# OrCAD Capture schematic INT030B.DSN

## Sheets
1 PAGE3: size B; title: TUSB542EVM INT030 Rev B: Power; rev: B; note: 6592044
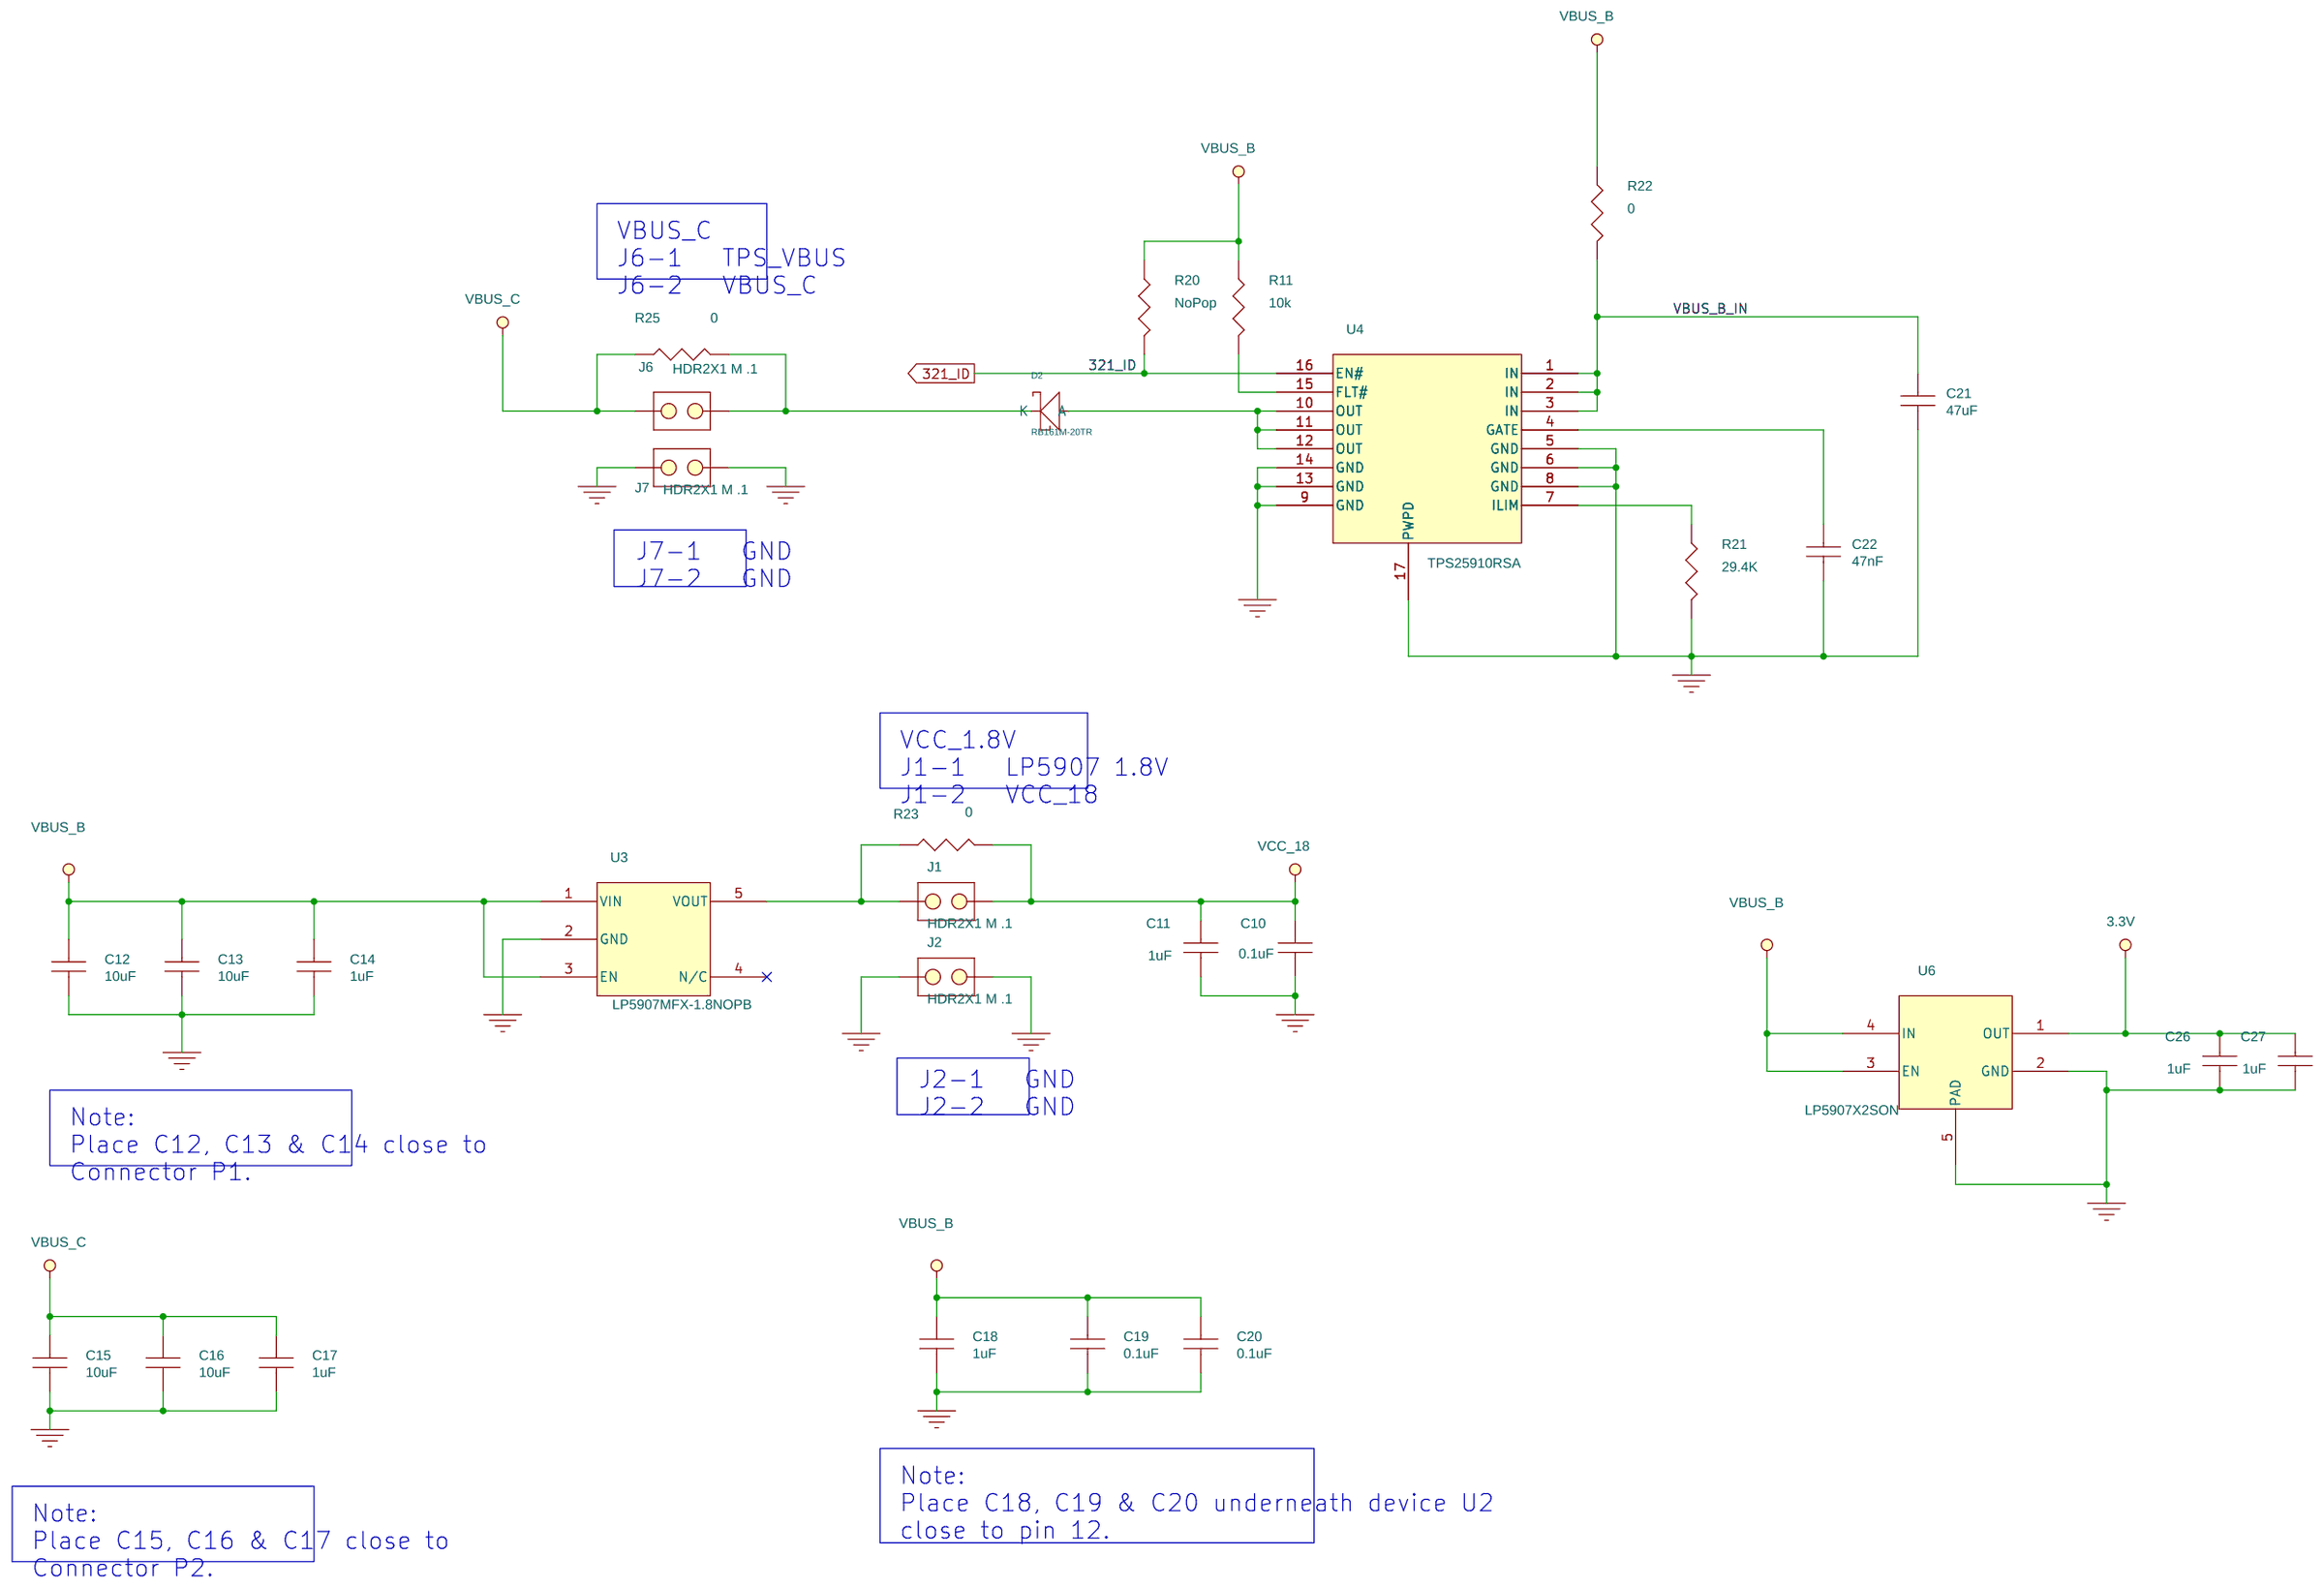
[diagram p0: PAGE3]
2 PAGE2: size C; title: TUSB542EVM INT030 Rev B
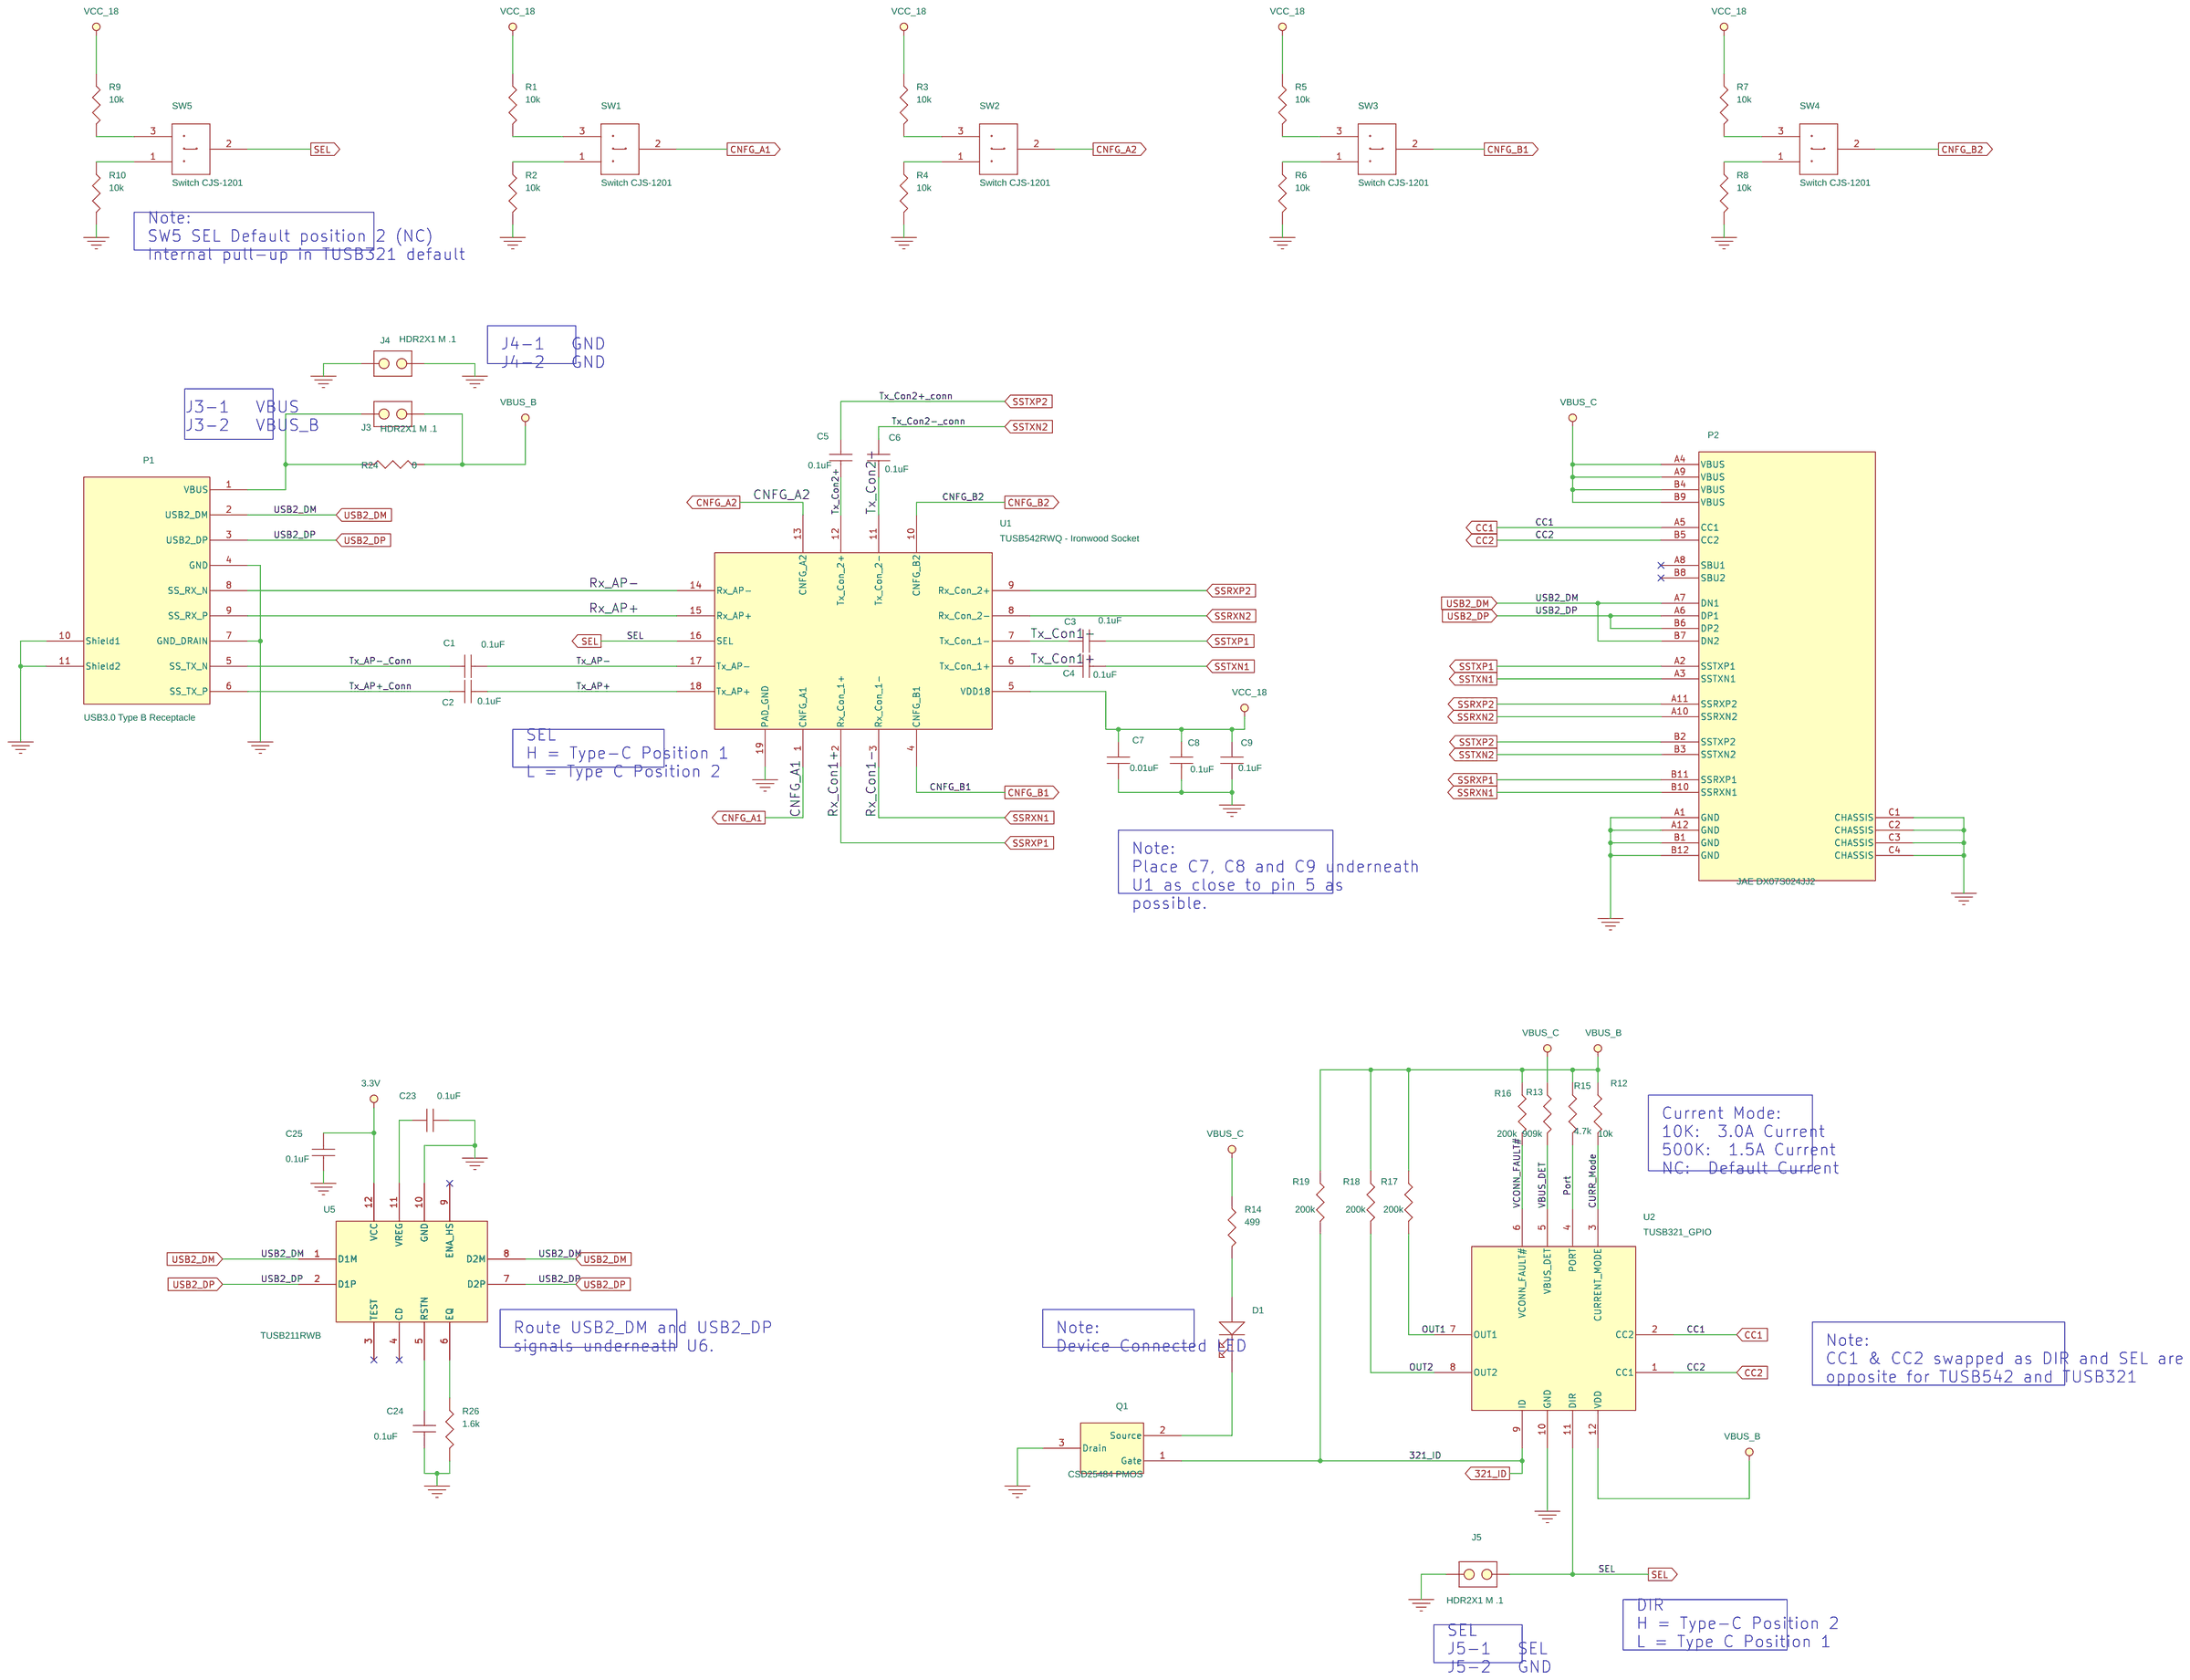
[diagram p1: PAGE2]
3 PAGE1: size B; title: TUSB542EVM INT030 Rev B: Block
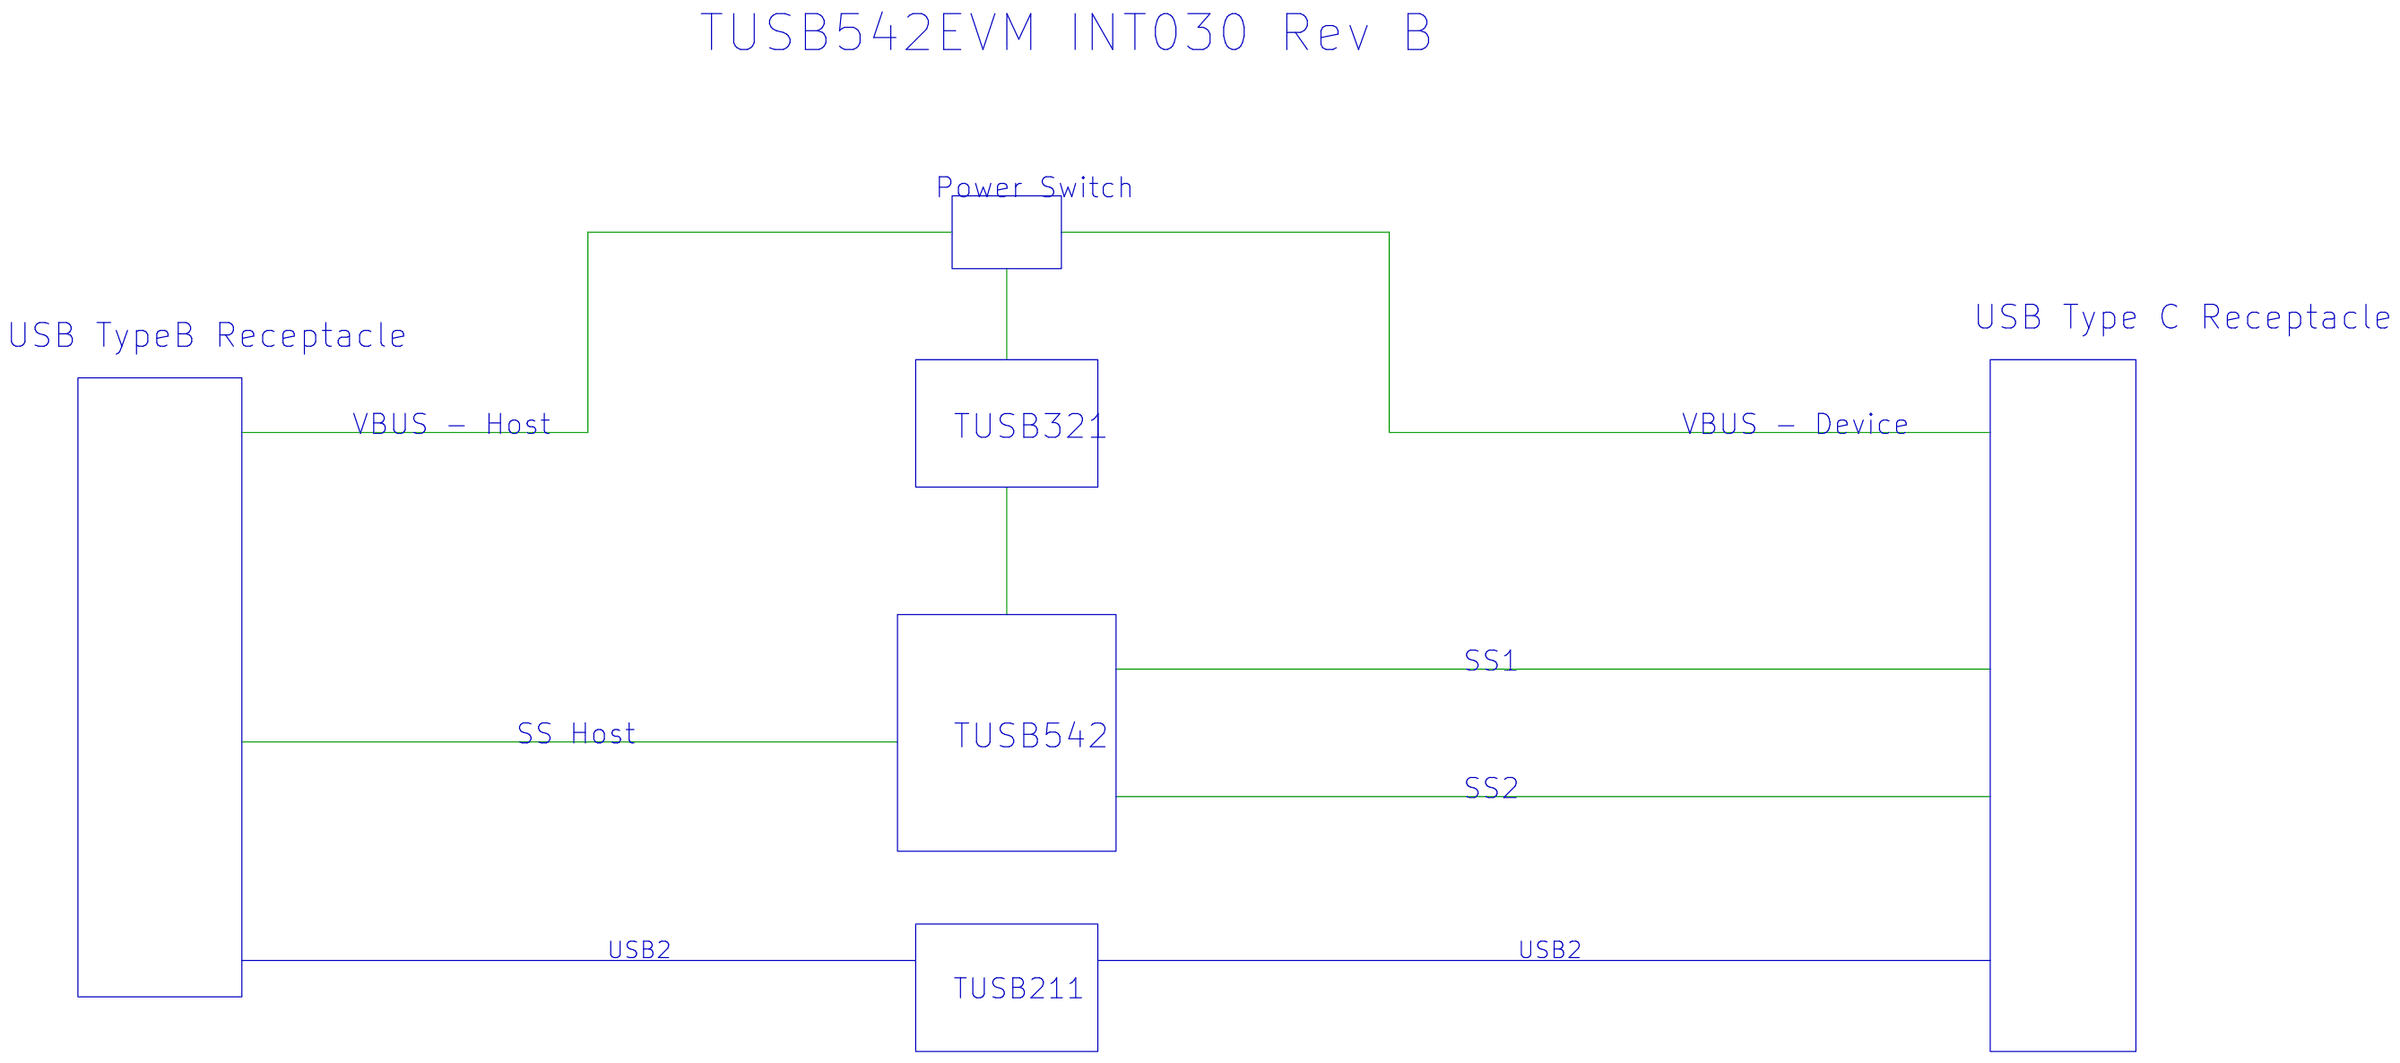
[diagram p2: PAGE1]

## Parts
sheet PAGE2
C1  0.1uF  [0201]
C2  0.1uF  [0201]
C3  0.1uF  [0201]
C4  0.1uF  [0201]
C5  0.1uF  [0201]
C6  0.1uF  [0201]
C7  0.01uF  [0201]
C8  0.1uF  [0201]
C9  0.1uF  [0201]
C23  0.1uF  [0201]
C24  0.1uF  [0201]
C25  0.1uF  [0201]
D1  LED  [LED_0805]
J3  HDR2X1 M .1  [HDR_THVT_1x2_100]
J4  HDR2X1 M .1  [HDR_THVT_1x2_100]
J5  HDR2X1 M .1  [HDR_THVT_1x2_100]
P1  USB3.0 Type B Receptacle  [USB3_TYPEB_AK4AA009]
P2  JAE DX07S024JJ2
Q1  CSD25484 PMOS  [YJJ_DFN_3]
R1  10k  [0402]
R2  10k  [0402]
R3  10k  [0402]
R4  10k  [0402]
R5  10k  [0402]
R6  10k  [0402]
R7  10k  [0402]
R8  10k  [0402]
R9  10k  [0402]
R10  10k  [0402]
R12  10k  [0402]
R13  909k  [0402]
R14  499  [0402]
R15  4.7k  [0402]
R16  200k  [0402]
R17  200k  [0402]
R18  200k  [0402]
R19  200k  [0402]
R24  0  [0805]
R26  1.6k  [0201]
SW1  Switch CJS-1201  [CJS-1200B]
SW2  Switch CJS-1201  [CJS-1200B]
SW3  Switch CJS-1201  [CJS-1200B]
SW4  Switch CJS-1201  [CJS-1200B]
SW5  Switch CJS-1201  [CJS-1200B]
U1  TUSB542RWQ - Ironwood Socket  [SKT_Ironwood_C14524]
U2  TUSB321_GPIO  [RWB]
U5  TUSB211RWB  [RWB]
sheet PAGE3
C10  0.1uF  [0402]
C11  1uF  [0402]
C12  10uF  [0603]
C13  10uF  [0603]
C14  1uF  [0402]
C15  10uF  [0603]
C16  10uF  [0603]
C17  1uF  [0402]
C18  1uF  [0402]
C19  0.1uF  [0201]
C20  0.1uF  [0201]
C21  47uF  [1206]
C22  47nF  [0402]
C26  1uF  [0402]
C27  1uF  [0402]
D2  SCHOTTKY  [SOD_123FL]
J1  HDR2X1 M .1  [HDR_THVT_1x2_100]
J2  HDR2X1 M .1  [HDR_THVT_1x2_100]
J6  HDR2X1 M .1  [HDR_THVT_1x2_100]
J7  HDR2X1 M .1  [HDR_THVT_1x2_100]
R11  10k  [0402]
R20  NoPop  [0402]
R21  29.4K  [0402]
R22  0  [0805]
R23  0  [0805]
R25  0  [0805]
U3  LP5907MFX-1.8NOPB  [DBV_R-PDSO-G5]
U4  TPS25910RSA  [QFN_16_161x161_26]
U6  LP5907X2SON  [DQN_X2SON_4]

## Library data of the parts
C1-C9 C19 C20 C23-C25 = cc0201
D1 = d0805_Green
J1-J7 = HDR2X1_M_.1
P1 = USB_3_0.0_Type_B_Receptacle
P2 = TypeC_JAE_TopMNT
Q1 = CSD25484F4
R1-R10 R12-R19 = r0402
R23-R25 = r0805
R26 = r0201
SW1-SW5 = Switch_CJS-1201
U1 = TUSB542RWQ
U2 = TUSB321_GPIO
U5 = TUSB211RWB
C10 C11 C14 C17 C18 C26 C27 = cc0402
C12 C13 C15 C16 = cc0603
C21 = CAP_NP: 10V Capacitor
C22 = CAP_NP: 6.3V Capacitor
D2 = SCHOTTKY: Diode; $SEC: 1; CDS_LIB: diode; CURRENT: 1A; DEVICE_NAME: RB161M-20TR; DRAWING: @LIGHTNING_BOLT_NB_LIB.NOTE_BOOK(SCH_1):PAGE1; Digi-Key Part Number: RB161M-20CT-ND; Manufacturer: Rohm Semiconductor; Manufacturer Part Number: RB161M-20TR; Manufacturer's Part Number: RB161M-20TR; PHYS_PAGE: 1; ROT: 0; TOLERANCE: NA; VER: 1; VOLTAGE: 20V; XY: (-1750,3700)
R11 R20 R22 = R: Resistor; Tolerance: 5%
R21 = R: Resistor; Tolerance: 1%
U3 = LP5907
U4 = TPS25910RSA
U6 = LP5907X2SON

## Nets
3.3V: C25.2 C26.1 C27.1 U5.12(VCC) U6.1(OUT)
GND: C7.2 C8.2 C9.2 C10.2 C11.2 C12.2 C13.2 C14.2 C15.2 C16.2 C17.2 C18.2 C19.2 C20.2 C21.2 C22.2 C23.2 C24.2 C25.1 C26.2 C27.2 J2.1 J2.2 J4.1 J4.2 J5.2 J7.1 J7.2 P1.4(GND) P1.7(GND_DRAIN) P1.10(Shield1) P1.11(Shield2) P2.A1(GND) P2.A12(GND) P2.B1(GND) P2.B12(GND) P2.C1(CHASSIS) P2.C2(CHASSIS) P2.C3(CHASSIS) P2.C4(CHASSIS) Q1.3(Drain) R2.2 R4.2 R6.2 R8.2 R10.2 R21.2 R26.2 U1.19(PAD_GND) U2.10(GND) U3.2(GND) U4.5(GND) U4.6(GND) U4.8(GND) U4.9(GND) U4.13(GND) U4.14(GND) U4.17(PWPD) U5.10(GND) U6.2(GND) U6.5(PAD)
VBUS_B: C12.1 C13.1 C14.1 C18.1 C19.1 C20.1 J3.2 R11.1 R12.1 R15.1 R16.1 R17.1 R18.1 R19.1 R20.1 R22.1 R24.2 U2.12(VDD) U3.1(VIN) U3.3(EN) U6.3(EN) U6.4(IN)
VBUS_B_IN: C21.1 R22.2 U4.1(IN) U4.2(IN) U4.3(IN)
VBUS_C: C15.1 C16.1 C17.1 J6.1 P2.A4(VBUS) P2.A9(VBUS) P2.B4(VBUS) P2.B9(VBUS) R13.1 R14.1 R25.1
VBUS_DET: R13.2 U2.5(VBUS_DET)
VCC_18: C7.1 C8.1 C9.1 C10.1 C11.1 J1.2 R1.1 R3.1 R5.1 R7.1 R9.1 R23.2 U1.5(VDD18)
321_ID: Q1.1(Gate) R19.2 R20.2 U2.9(ID) U4.16(EN#)
CC1: P2.A5(CC1) U2.2(CC2)
CC2: P2.B5(CC2) U2.1(CC1)
CNFG_A1: SW1.2 U1.1(CNFG_A1)
CNFG_A2: SW2.2 U1.13(CNFG_A2)
CNFG_B1: SW3.2 U1.4(CNFG_B1)
CNFG_B2: SW4.2 U1.10(CNFG_B2)
CURR_Mode: R12.2 U2.3(CURRENT_MODE)
OUT1: R17.2 U2.7(OUT1)
OUT2: R18.2 U2.8(OUT2)
Port: R15.2 U2.4(PORT)
Rx_AP+: P1.9(SS_RX_P) U1.15(Rx_AP+)
Rx_AP-: P1.8(SS_RX_N) U1.14(Rx_AP-)
SEL: J5.1 SW5.2 U1.16(SEL) U2.11(DIR)
SSRXN1: P2.B10(SSRXN1) U1.3(Rx_Con_1-)
SSRXN2: P2.A10(SSRXN2) U1.8(Rx_Con_2-)
SSRXP1: P2.B11(SSRXP1) U1.2(Rx_Con_1+)
SSRXP2: P2.A11(SSRXP2) U1.9(Rx_Con_2+)
SSTXN1: C4.2 P2.A3(SSTXN1)
SSTXN2: C6.1 P2.B3(SSTXN2)
SSTXP1: C3.2 P2.A2(SSTXP1)
SSTXP2: C5.1 P2.B2(SSTXP2)
Tx_AP+: C2.2 U1.18(Tx_AP+)
Tx_AP+_Conn: C2.1 P1.6(SS_TX_P)
Tx_AP-: C1.2 U1.17(Tx_AP-)
Tx_AP-_Conn: C1.1 P1.5(SS_TX_N)
Tx_Con1+: C4.1 U1.6(Tx_Con_1+)
Tx_Con1-: C3.1 U1.7(Tx_Con_1-)
Tx_Con2+: C5.2 U1.12(Tx_Con_2+)
Tx_Con2-: C6.2 U1.11(Tx_Con_2-)
USB2_DM: P1.2(USB2_DM) P2.A7(DN1) P2.B7(DN2) U5.1(D1M) U5.8(D2M)
USB2_DP: P1.3(USB2_DP) P2.A6(DP1) P2.B6(DP2) U5.2(D1P) U5.7(D2P)
VCONN_FAULT#: R16.2 U2.6(VCONN_FAULT#)
N04611: J3.1 P1.1(VBUS) R24.1
N16552543: R1.2 SW1.3
N16552547: R2.1 SW1.1
N16552551: R3.2 SW2.3
N16552555: R4.1 SW2.1
N16552559: R5.2 SW3.3
N16552563: R6.1 SW3.1
N16552567: R7.2 SW4.3
N16552571: R8.1 SW4.1
N16553344: R10.1 SW5.1
N16553348: R9.2 SW5.3
N16554903: D1.2 R14.2
N16554907: D1.1 Q1.2(Source)
N16595246: R11.2 U4.15(FLT#)
N16595298: D2.2(A) U4.10(OUT) U4.11(OUT) U4.12(OUT)
N16595310: R21.1 U4.7(ILIM)
N16595320: C22.1 U4.4(GATE)
N16602154: J1.1 R23.1 U3.5(VOUT)
N16604263: C23.1 U5.11(VREG)
N16604411: C24.1 U5.5(RSTN)
N16604415: R26.1 U5.6(EQ)
N16616318: D2.1(K) J6.2 R25.2

Not connected (* = marked no-connect by the designer): P2 A8(SBU1)* B8(SBU2)*; U3 4(N/C)*; U5 3(TEST)* 4(CD)* 9(ENA_HS)*

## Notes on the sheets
sheet 1
- VBUS_C
  J6-1   TPS_VBUS
  J6-2   VBUS_C
- J7-1   GND
  J7-2   GND
- VCC_1.8V
  J1-1   LP5907 1.8V
  J1-2   VCC_18
- J2-1   GND
  J2-2   GND
- Note:
  Place C12, C13 & C14 close to
  Connector P1.
- Note:
  Place C18, C19 & C20 underneath device U2
  close to pin 12.
- Note:
  Place C15, C16 & C17 close to
  Connector P2.
sheet 2
- Note:
  SW5 SEL Default position 2 (NC)
  Internal pull-up in TUSB321 default
- J4-1   GND
  J4-2   GND
- J3-1   VBUS
  J3-2   VBUS_B
- SEL
  H = Type-C Position 1
  L = Type C Position 2
- Note:
  Place C7, C8 and C9 underneath
  U1 as close to pin 5 as
  possible.
- Current Mode:
  10K:  3.0A Current
  500K:  1.5A Current
  NC:  Default Current
- Route USB2_DM and USB2_DP
  signals underneath U6.
- Note:
  Device Connected LED
- Note:
  CC1 & CC2 swapped as DIR and SEL are
  opposite for TUSB542 and TUSB321
- DIR
  H = Type-C Position 2
  L = Type C Position 1
- SEL
  J5-1   SEL
  J5-2   GND
sheet 3
- TUSB542EVM INT030 Rev B
- Power Switch
- USB Type C Receptacle
- USB TypeB Receptacle
- VBUS - Host
- TUSB321
- VBUS - Device
- SS1
- SS Host
- TUSB542
- SS2
- USB2
- USB2
- TUSB211
